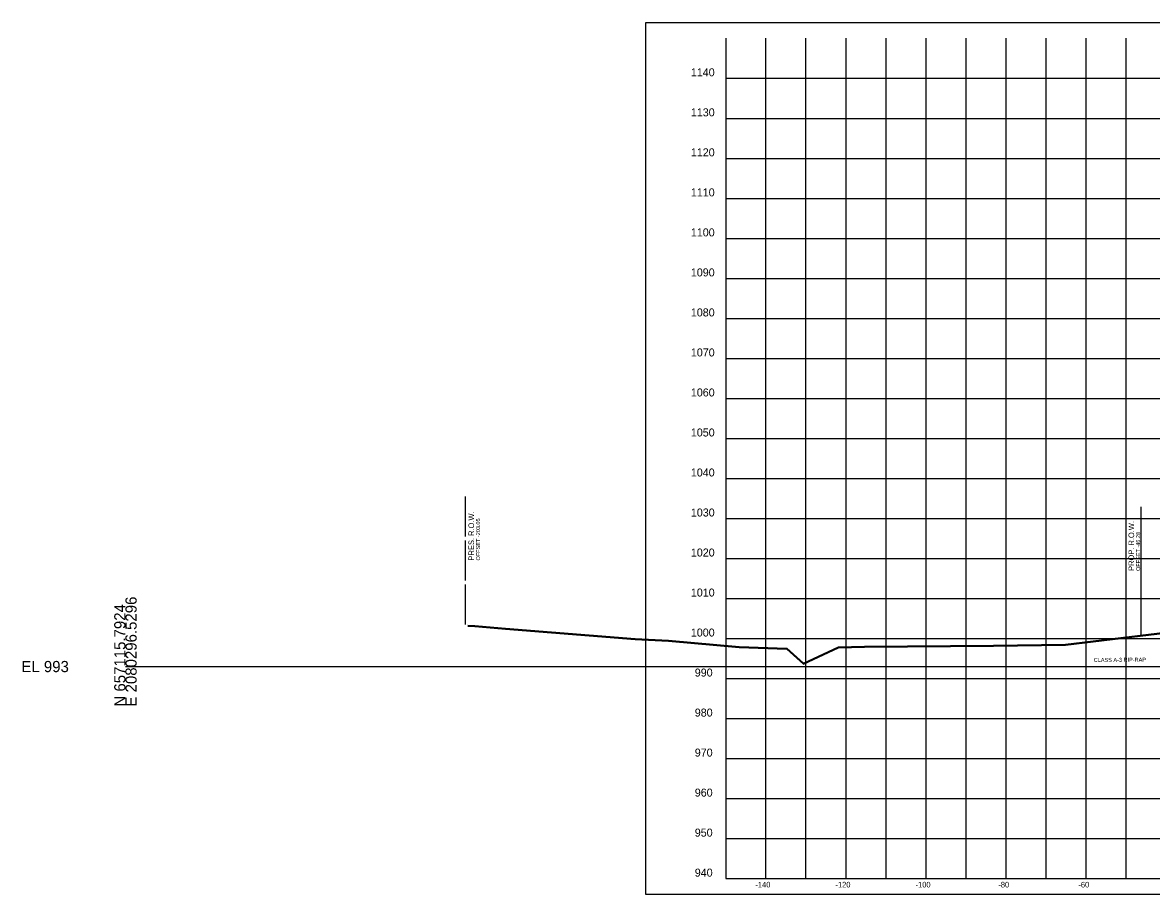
# Model space of a CAD drawing. Extents: x 1131015 to 1136271, y 133453 to 174329.
# Drawn here: x 1132014.8 to 1132296.8, y 159110.7 to 159328.6 of the extents above; entities that cross this region are included whole.
import ezdxf

# ---------------------------------------------------------------- set-up
doc = ezdxf.new("R2010")
doc.units = 0
for name, color, linetype in [('DESIGN - ROW - Right-of-Way and Easement Labels', 7, 'Continuous'), ('DESIGN - ROW - Right-of-Way Linework', 7, 'Continuous'), ('DESIGN - SHEET - Corner Text', 7, 'Continuous'), ('DESIGN - SHEET - Light Grid', 7, 'Continuous'), ('DESIGN - SHEET - Linework', 7, 'Continuous'), ('DESIGN - SHEET - Plot Shape', 7, 'Continuous'), ('DESIGN - TYPICAL - Finished Grade Slopes Text', 7, 'Continuous'), ('SURVEY - GROUND - Bottom of Topsoil Layer', 7, 'Continuous'), ('SURVEY - GROUND - Top of Ground', 7, 'Continuous'), ('SURVEY - PROPERTY - ROW Lines', 7, 'Continuous'), ('SURVEY - PROPERTY - ROW Lines Text', 7, 'Continuous')]:
    doc.layers.add(name, color=color, linetype=linetype)

msp = doc.modelspace()

# ---------------------------------------------------------------- linework, layer by layer
at = {"layer": 'DESIGN - ROW - Right-of-Way Linework'}
msp.add_line((1132294.18, 159175.55), (1132294.18, 159207.55), dxfattribs=at)
at = {"layer": 'DESIGN - SHEET - Light Grid'}
msp.add_line((1132040.46, 159167.66), (1132340.46, 159167.66), dxfattribs=at)
at = {"layer": 'DESIGN - SHEET - Linework'}
for p, q in [((1132200.46, 159114.66), (1132200.46, 159324.66)), ((1132210.46, 159114.66), (1132210.46, 159324.66)), ((1132220.46, 159114.66), (1132220.46, 159324.66)), ((1132230.46, 159114.66), (1132230.46, 159324.66)), ((1132240.46, 159114.66), (1132240.46, 159324.66)), ((1132250.46, 159114.66), (1132250.46, 159324.66)), ((1132260.46, 159114.66), (1132260.46, 159324.66)), ((1132270.46, 159114.66), (1132270.46, 159324.66)), ((1132280.46, 159114.66), (1132280.46, 159324.66)), ((1132290.46, 159114.66), (1132290.46, 159324.66)), ((1132190.46, 159314.66), (1132490.46, 159314.66)), ((1132190.46, 159304.66), (1132490.46, 159304.66)), ((1132190.46, 159294.66), (1132490.46, 159294.66)), ((1132190.46, 159284.66), (1132490.46, 159284.66)), ((1132190.46, 159274.66), (1132490.46, 159274.66)), ((1132190.46, 159264.66), (1132490.46, 159264.66)), ((1132190.46, 159254.66), (1132490.46, 159254.66)), ((1132190.46, 159244.66), (1132490.46, 159244.66)), ((1132190.46, 159234.66), (1132490.46, 159234.66)), ((1132190.46, 159224.66), (1132490.46, 159224.66)), ((1132190.46, 159214.66), (1132490.46, 159214.66)), ((1132190.46, 159204.66), (1132490.46, 159204.66)), ((1132190.46, 159194.66), (1132490.46, 159194.66)), ((1132190.46, 159184.66), (1132490.46, 159184.66)), ((1132190.46, 159174.66), (1132490.46, 159174.66)), ((1132190.46, 159164.66), (1132490.46, 159164.66)), ((1132190.46, 159154.66), (1132490.46, 159154.66)), ((1132190.46, 159144.66), (1132490.46, 159144.66)), ((1132190.46, 159134.66), (1132490.46, 159134.66)), ((1132190.46, 159124.66), (1132490.46, 159124.66))]:
    msp.add_line(p, q, dxfattribs=at)
msp.add_lwpolyline([(1132190.46, 159324.66), (1132190.46, 159114.66), (1132490.46, 159114.66), (1132490.46, 159324.66)], dxfattribs=at)
at = {"layer": 'DESIGN - SHEET - Plot Shape'}
msp.add_lwpolyline([(1132170.46, 159328.6), (1132510.46, 159328.6), (1132510.46, 159110.72), (1132170.46, 159110.72)], close=True, dxfattribs=at)
at = {"layer": 'SURVEY - GROUND - Bottom of Topsoil Layer'}
for p, q in [((1132125.96, 159177.78), (1132127.77, 159177.66)), ((1132127.77, 159177.66), (1132135.4, 159176.97)), ((1132135.4, 159176.97), (1132167.83, 159174.44)), ((1132167.83, 159174.44), (1132176.1, 159174.01)), ((1132176.1, 159174.01), (1132193.8, 159172.43)), ((1132275.29, 159173.03), (1132302.89, 159176.35)), ((1132193.8, 159172.43), (1132205.65, 159171.98)), ((1132205.65, 159171.98), (1132209.8, 159168.24)), ((1132209.8, 159168.24), (1132218.57, 159172.35)), ((1132218.57, 159172.35), (1132225.06, 159172.53)), ((1132225.06, 159172.53), (1132257.3, 159172.76)), ((1132257.3, 159172.76), (1132275.29, 159173.03))]:
    msp.add_line(p, q, dxfattribs=at)
at = {"layer": 'SURVEY - GROUND - Top of Ground'}
for p, q in [((1132125.96, 159178.03), (1132127.77, 159177.91)), ((1132127.77, 159177.91), (1132135.4, 159177.22)), ((1132135.4, 159177.22), (1132167.83, 159174.69)), ((1132275.29, 159173.28), (1132302.89, 159176.6)), ((1132167.83, 159174.69), (1132176.1, 159174.26)), ((1132176.1, 159174.26), (1132193.8, 159172.68)), ((1132193.8, 159172.68), (1132205.65, 159172.23)), ((1132205.65, 159172.23), (1132209.8, 159168.49)), ((1132209.8, 159168.49), (1132218.57, 159172.6)), ((1132218.57, 159172.6), (1132225.06, 159172.78)), ((1132225.06, 159172.78), (1132257.3, 159173.01)), ((1132257.3, 159173.01), (1132275.29, 159173.28))]:
    msp.add_line(p, q, dxfattribs=at)
at = {"layer": 'SURVEY - PROPERTY - ROW Lines'}
for p, q in [((1132125.4, 159200.17), (1132125.4, 159210.17)), ((1132125.4, 159189.17), (1132125.4, 159199.17)), ((1132125.4, 159178.17), (1132125.4, 159188.17))]:
    msp.add_line(p, q, dxfattribs=at)

# ---------------------------------------------------------------- texts
at = {"layer": 'DESIGN - ROW - Right-of-Way and Easement Labels'}
for s, height, p in [('PROP. R.O.W.', 1.4, (1132292.43, 159191.55)), ('OFFSET -46.28', 1, (1132293.93, 159191.55))]:
    msp.add_text(s, height=height, rotation=90, dxfattribs=at).set_placement(p)
at = {"layer": 'DESIGN - SHEET - Corner Text'}
for s, height, p in [('1140', 2, (1132181.7, 159315.16)), ('1130', 2, (1132181.7, 159305.16)), ('1120', 2, (1132181.7, 159295.16)), ('1110', 2, (1132181.7, 159285.16)), ('1100', 2, (1132181.7, 159275.16)), ('1090', 2, (1132181.7, 159265.16)), ('1080', 2, (1132181.7, 159255.16)), ('1070', 2, (1132181.7, 159245.16)), ('1060', 2, (1132181.7, 159235.16)), ('1050', 2, (1132181.7, 159225.16)), ('1040', 2, (1132181.7, 159215.16)), ('1030', 2, (1132181.7, 159205.16)), ('1020', 2, (1132181.7, 159195.16)), ('1010', 2, (1132181.7, 159185.16)), ('1000', 2, (1132181.7, 159175.16)), ('990', 2, (1132182.68, 159165.16)), ('980', 2, (1132182.68, 159155.16)), ('970', 2, (1132182.68, 159145.16)), ('960', 2, (1132182.68, 159135.16)), ('950', 2, (1132182.68, 159125.16)), ('940', 2, (1132182.68, 159115.16)), ('-140', 1.4, (1132197.83, 159112.46)), ('-120', 1.4, (1132217.83, 159112.46)), ('-100', 1.4, (1132237.83, 159112.46)), ('-80', 1.4, (1132258.51, 159112.46)), ('-60', 1.4, (1132278.51, 159112.46))]:
    msp.add_text(s, height=height, dxfattribs=at).set_placement(p)
at = {"layer": 'DESIGN - SHEET - Light Grid'}
for s, p in [('E 2080296.5296', (1132043.26, 159157.66)), ('N 657115.7924', (1132040.46, 159157.66))]:
    msp.add_text(s, height=2.8, rotation=90, dxfattribs=at).set_placement(p)
msp.add_text('EL 993', height=2.8, dxfattribs=at).set_placement((1132014.46, 159166.26))
at = {"layer": 'DESIGN - TYPICAL - Finished Grade Slopes Text'}
msp.add_text('CLASS A-3 RIP-RAP', height=1, rotation=0.2814, dxfattribs=at).set_placement((1132282.35, 159168.81))
at = {"layer": 'SURVEY - PROPERTY - ROW Lines Text'}
for s, height, p in [('PRES. R.O.W.', 1.4, (1132127.55, 159194.17)), ('OFFSET -203.05', 1, (1132129.05, 159194.17))]:
    msp.add_text(s, height=height, rotation=90, dxfattribs=at).set_placement(p)

doc.saveas('drawing.dxf')
